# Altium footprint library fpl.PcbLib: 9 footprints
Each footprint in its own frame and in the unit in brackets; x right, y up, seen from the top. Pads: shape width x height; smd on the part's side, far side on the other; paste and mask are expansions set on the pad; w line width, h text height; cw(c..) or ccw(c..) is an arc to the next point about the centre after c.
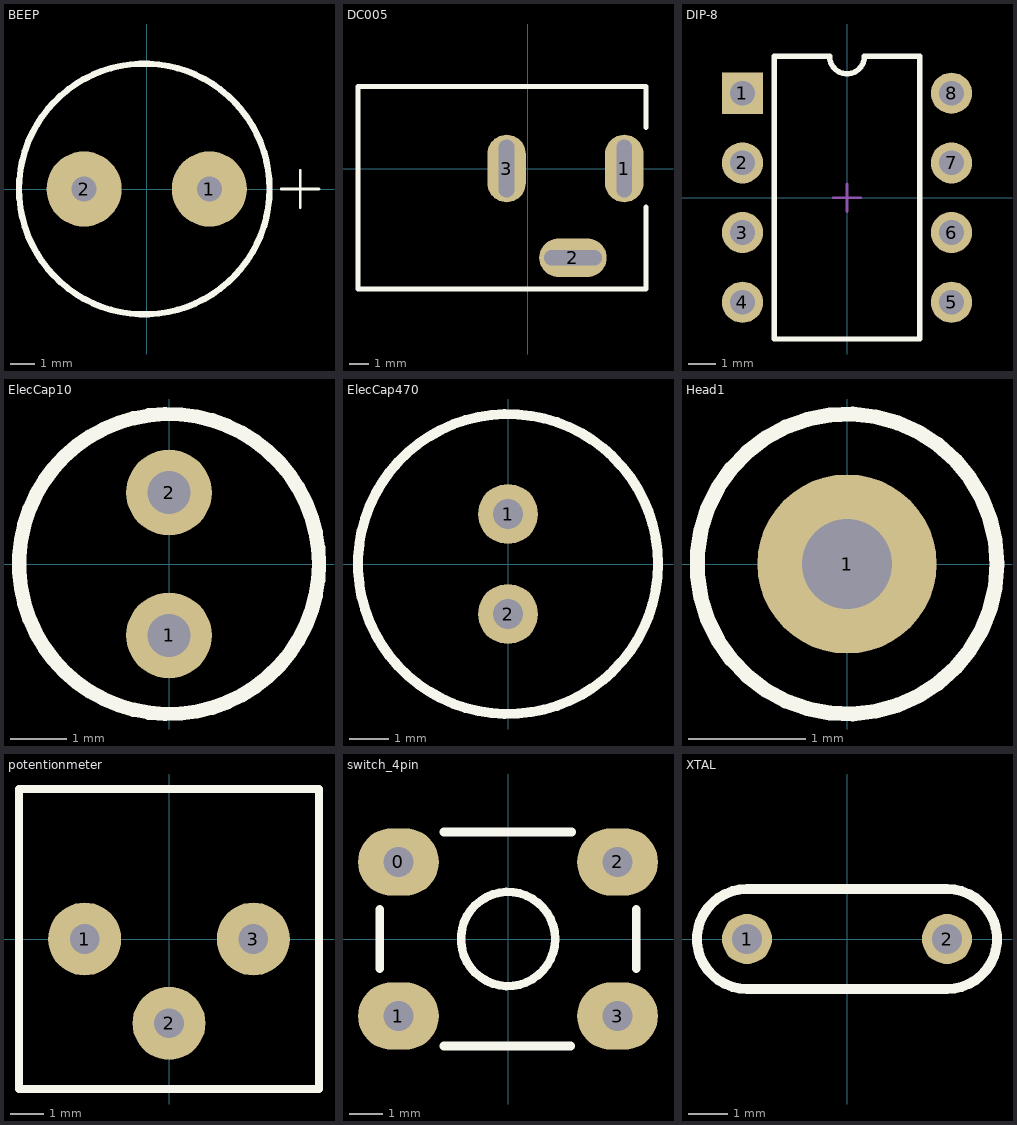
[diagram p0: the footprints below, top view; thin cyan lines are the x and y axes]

## BEEP [mil] "蜂鸣器"
height 300
pads (2):
  round 120 hole 40: 1(100,0) 2(-100,0)
Top Overlay:
  circle w10: c-3.89,0 r200
  lines w4: 215,0 275,0 ; 245,-30 245,30

## DC005 [mil] "2.1mmDC插座"
height 393.7
pads (3):
  oval 80x140 hole 32 slot 120 at 90 deg: 1(200,0) 3(-44,0)
  oval 140x80 hole 32 slot 120 at 0 deg: 2(93.7,-185)
Top Overlay:
  lines w10: 245,-80 245,-250 -352,-250 -352,170 245,170 245,85

## DIP-8 [mm]
pads (8):
  rect 1.5x1.5 hole 0.9: 1(-3.81,3.81)
  round 1.5 hole 0.9: 2(-3.81,1.27) 3(-3.81,-1.27) 4(-3.81,-3.81) 5(3.81,-3.81) 6(3.81,-1.27) 7(3.81,1.27) 8(3.81,3.81)
Top Overlay:
  lines w0.2: -2.65,-5.15 2.65,-5.15 2.65,5.15 0.635,5.15 cw(c0,5.15) -0.635,5.15 -2.65,5.15 -2.65,-5.15
Mechanical 15:
  lines w0.1: -0.5,0 0.5,0 ; 0,-0.5 0,0.5

## ElecCap10 [mil] "10uF电解电容"
height 300
pads (2):
  round 60 hole 30: 1(0,-50) 2(0,50)
Top Overlay:
  circle w10: c0,0 r105

## ElecCap470 [mil] "470uF电解电容"
height 300
pads (2):
  round 60 hole 30: 1(0,50) 2(0,-50)
Top Overlay:
  circle w10: c0,0 r150

## Head1 [mil] "1pin焊盘"
pads (1):
  round 60 hole 30: 1(0,0)
Top Overlay:
  circle w5: c0,0 r50.25

## potentionmeter [mm] "电位计"
pads (3):
  round 2.2 hole 0.9: 1(-2.54,0) 2(0,-2.54) 3(2.54,0)
Top Overlay:
  lines w0.254: -4.521,-4.521 -4.521,4.521 4.521,4.521 4.521,-4.521 -4.521,-4.521

## switch_4pin [mm] "单稳态按钮开关"
pads (4):
  oval 2.4x2 hole 0.9: 0(-3.251,2.286) 1(-3.251,-2.286) 2(3.251,2.286) 3(3.251,-2.286)
Top Overlay:
  circle w0.254: c0,0 r1.397
  lines w0.254: -3.81,-0.889 -3.81,0.889 ; -1.905,-3.175 1.864,-3.175 ; -1.905,3.175 1.889,3.175 ; 3.81,-0.889 3.81,0.889

## XTAL [mil] "晶振"
pads (2):
  round 50 hole 30: 1(-100,0) 2(100,0)
Top Overlay:
  lines w10: -100,-50 cw(c-100,0) -100,50 100,50 cw(c100,0) 100,-50 -100,-50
